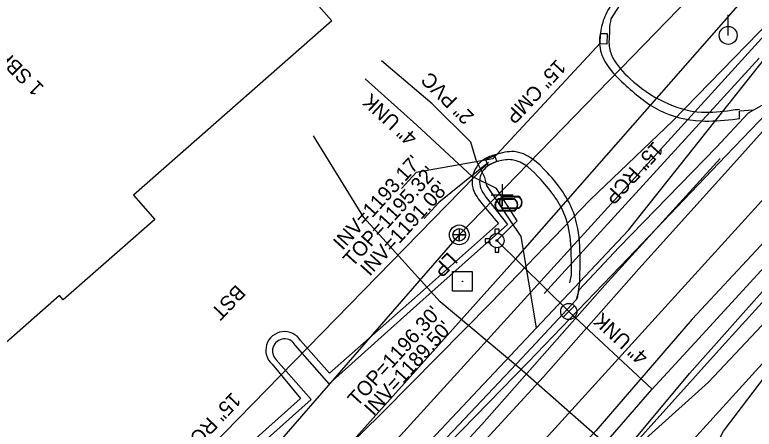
# Model space of a CAD drawing. Extents: x 1263837 to 1268319, y 770628 to 773628.
# Drawn here: x 1266878 to 1267080.4, y 772434.2 to 772547.7 of the extents above; entities that cross this region are included whole.
import ezdxf

# ---------------------------------------------------------------- set-up
doc = ezdxf.new("R2010")
doc.units = 0
for name, color, linetype in [('Exist Building', 7, 'Continuous'), ('Exist Building Text', 7, 'Continuous'), ('Exist DTM Spot Elevation CELL', 7, 'Continuous'), ('Exist Roads EOT Text', 7, 'Continuous'), ('Exist Structure Minor Catch Basin', 7, 'Continuous'), ('Exist Structure Minor Catch Basin Top Elevation', 7, 'Continuous'), ('Exist Utilities Gas UG Line SUE LOS B', 7, 'Continuous'), ('Exist Utilities Gas UG Line SUE LOS B Text', 7, 'Continuous'), ('Exist Utilities Other Pole With Base CELL', 7, 'Continuous'), ('Exist Utilities Other Pole With Base Text', 7, 'Continuous'), ('Exist Utilities Power Pole CELL', 7, 'Continuous'), ('Exist Utilities Telephone UG Cable SUE LOS B', 7, 'Continuous'), ('Exist Utilities Telephone UG FO SUE LOS B', 7, 'Continuous'), ('Exist Utilities TV UG Cable SUE LOS B', 7, 'Continuous'), ('Exist Utilities Water Fire Hydrant CELL', 7, 'Continuous'), ('Exist Utilities Water Meter CELL', 7, 'Continuous'), ('Exist Utilities Water UG Line SUE LOS B', 7, 'Continuous'), ('Exist Utilities Water UG Line SUE LOS B Text', 7, 'Continuous'), ('Exist Utilities Water Valve CELL', 7, 'Continuous'), ('Prop Conc 1ft 6in Curb and Gutter', 7, 'Continuous'), ('Prop Conc 5in Monolithic Keyed In Island', 7, 'Continuous'), ('Prop Drainage Structure Junction Box with Slab Lid Label', 7, 'Continuous'), ('Prop Drainage Structure Pipe RCP 15in Class III Label', 7, 'Continuous'), ('Prop Drainage Structure Pipe RCP 24in Class III Label', 7, 'Continuous'), ('Prop Drainage Structure Pipe Removal Label', 7, 'Continuous'), ('Prop Horizontal Alignment', 7, 'Continuous'), ('Prop Retaining Wall', 7, 'Continuous'), ('Prop SS Fill Line', 7, 'Continuous'), ('Prop SS Fill Text', 7, 'Continuous'), ('Prop SS Transition Line', 7, 'Continuous'), ('Prop WCC CELL', 7, 'Continuous'), ('Prop WCR CELL', 7, 'Continuous'), ('Scratch_Level_2', 7, 'Continuous'), ('Scratch_Level_5', 7, 'Continuous'), ('Typical Terminator CELL', 7, 'Continuous')]:
    doc.layers.add(name, color=color, linetype=linetype)

# ---------------------------------------------------------------- blocks, each defined once
blk = doc.blocks.new('EXIST UTILITIES SANITARY SEWER MANHOLE')
at = {"layer": 'Prop WCR CELL'}
blk.add_lwpolyline([(0, 0.03425), (0, -0.03425), (0, 0), (0.03425, 0), (-0.03425, 0)], dxfattribs=at)
for radius in [0.05389, 0.03425]:
    blk.add_circle((0, 0), radius, dxfattribs=at)
blk = doc.blocks.new('EXIST UTILITIES OTHER POLE WITH BASE')
at = {"layer": 'Exist Utilities Other Pole With Base CELL'}
blk.add_line((0, 0), (0, 0), dxfattribs=at)
blk.add_lwpolyline([(-0.0545, 0.054), (0.0535, 0.054), (0.0535, -0.054), (-0.0545, -0.054), (-0.0545, 0.054)], dxfattribs=at)
blk.add_circle((0, 0), 0.00141, dxfattribs=at)
blk = doc.blocks.new('EXIST DTM SPOT ELEVATION')
at = {"layer": 'Exist DTM Spot Elevation CELL'}
blk.add_lwpolyline([(0, 0.06), (0, -0.06), (0, 0), (0.06, 0), (-0.06, 0)], dxfattribs=at)
blk = doc.blocks.new('EXIST UTILITIES POWER POLE')
at = {"layer": 'Exist Utilities Power Pole CELL'}
for q in [(0, 0.1125), (0, 0)]:
    blk.add_line((0, 0), q, dxfattribs=at)
blk.add_circle((0, 0), 0.049, dxfattribs=at)
blk = doc.blocks.new('EXIST UTILITIES WATER METER')
at = {"layer": 'Exist Utilities Water Meter CELL'}
blk.add_line((0, 0), (0, 0), dxfattribs=at)
for points in [[(-0.0408, 0.034), (0.0408, 0.034)], [(-0.0408, 0.0312), (0.0408, 0.0312)], [(0.0408, -0.0312), (-0.0413, -0.0312)], [(0.0408, -0.034), (-0.0413, -0.034)]]:
    blk.add_lwpolyline(points, dxfattribs=at)
for centre, radius, start, end in [((-0.0261, -0.0001), 0.0371, 113.178, 245.9794), ((-0.0259, -0.0001), 0.0347, 115.3009, 243.7824), ((0.0259, 0), 0.0371, 293.6483, 66.3084), ((0.0261, 0), 0.0345, 295.1272, 64.8728)]:
    blk.add_arc(centre, radius, start, end, dxfattribs=at)
blk = doc.blocks.new('EXIST UTILITIES WATER FIRE HYDRANT')
at = {"layer": 'Exist Utilities Water Fire Hydrant CELL'}
blk.add_line((0, 0), (0, 0), dxfattribs=at)
for points in [[(-0.01025, 0.03825), (-0.01025, 0.064), (0.01025, 0.064), (0.01025, 0.03775)], [(-0.03825, 0.01025), (-0.064, 0.01025), (-0.064, -0.01025), (-0.03825, -0.01025)], [(-0.01025, -0.03825), (-0.01025, -0.064), (0.01025, -0.064), (0.01025, -0.03775)]]:
    blk.add_lwpolyline(points, dxfattribs=at)
for radius in [0.03954, 0.00485]:
    blk.add_circle((0, 0), radius, dxfattribs=at)
blk = doc.blocks.new('EXIST UTILITIES WATER VALVE')
at = {"layer": 'Exist Utilities Water Valve CELL'}
blk.add_lwpolyline([(0.0315, 0.0315), (-0.0315, -0.0315), (0, 0), (0.0315, -0.0315), (-0.0315, 0.0315)], dxfattribs=at)
blk.add_circle((0, 0), 0.0445, dxfattribs=at)

msp = doc.modelspace()

# ---------------------------------------------------------------- linework, layer by layer
at = {"layer": 'Exist Building'}
for p, q in [((1266887.19, 772634.22), (1266964.78, 772546.07)), ((1266964.78, 772546.07), (1266910.49, 772498.29)), ((1266910.49, 772498.29), (1266916.33, 772491.66)), ((1266916.33, 772491.66), (1266891.31, 772469.64)), ((1266890.24, 772470.86), (1266867.63, 772450.96)), ((1266891.31, 772469.64), (1266890.24, 772470.86))]:
    msp.add_line(p, q, dxfattribs=at)
at = {"layer": 'Exist Structure Minor Catch Basin'}
for points in [[(1267038.27, 772539.75), (1267038.36, 772542.6), (1267040.15, 772542.55), (1267040.06, 772539.7)], [(1267006.86, 772508.11), (1267007.48, 772506.58), (1267010, 772507.61), (1267009.38, 772509.13)]]:
    msp.add_lwpolyline(points, close=True, dxfattribs=at)
at = {"layer": 'Exist Utilities Gas UG Line SUE LOS B'}
for points in [[(1267020.79, 772462.03), (1267045.96, 772488.76), (1267078.13, 772529.13), (1267092.32, 772547.17), (1267130.56, 772588.01), (1267171.7, 772635.15), (1267216.72, 772685.42), (1267246.23, 772719.28), (1267260.5, 772735.72), (1267305.1, 772784.15), (1267347.02, 772830.88), (1267365.09, 772851.17), (1267410.96, 772900.49)], [(1267020.79, 772462.03), (1267016.6, 772486.98), (1267007.2, 772500.95), (1267006.67, 772503.14), (1267004.32, 772507.87), (1267002.82, 772512.83), (1266992.27, 772523.31), (1266978.43, 772535.14)], [(1266826.01, 772260.15), (1266857.65, 772289.14), (1266895.03, 772326.45), (1266944.34, 772380.2), (1266987.5, 772426.58), (1267020.79, 772462.03)]]:
    msp.add_lwpolyline(points, dxfattribs=at)
at = {"layer": 'Exist Utilities Telephone UG Cable SUE LOS B'}
for points in [[(1267052.83, 772419.78), (1267044.36, 772426.17), (1267016.25, 772450.85), (1266994.43, 772469.13), (1266973.54, 772492.2), (1266959.83, 772514.6)], [(1266894.85, 772231.77), (1266893.08, 772233.4), (1266890.92, 772236.91), (1266894.43, 772241.95), (1266895.81, 772246.91), (1266901.85, 772256.59), (1266913.6, 772269.64), (1266885.36, 772298.67), (1266907.53, 772324.36), (1266940.1, 772361.84), (1266971, 772397.71), (1267005.88, 772435.55), (1267039.51, 772473.7), (1267071.13, 772508.4)], [(1266894.82, 772231.62), (1266882.54, 772238.29), (1266881.5, 772240.54), (1266906.85, 772271.5), (1266931.58, 772297.61), (1266956.08, 772328.45), (1266980.39, 772357.69), (1266998.14, 772378.22), (1267038.01, 772420.21), (1267067.86, 772447.15), (1267100, 772481.26)]]:
    msp.add_lwpolyline(points, dxfattribs=at)
at = {"layer": 'Exist Utilities Telephone UG FO SUE LOS B'}
for points in [[(1266814.85, 772276.3), (1266828.4, 772281.15), (1266850.03, 772305.04), (1266875.42, 772334.02), (1266901.87, 772361.16), (1266928.35, 772388.2), (1266955.12, 772415.65), (1266978.94, 772439.07), (1267008.37, 772468.81), (1267035.48, 772497.08), (1267058.14, 772518.7), (1267085.04, 772546.33), (1267108.31, 772568.88), (1267130.45, 772592.84), (1267151.19, 772617.71), (1267175.93, 772646.52), (1267201.12, 772673.74)], [(1267052.83, 772419.78), (1267051.59, 772421.75), (1267044.97, 772428.27), (1267062.65, 772449.51), (1267094.39, 772485.05)]]:
    msp.add_lwpolyline(points, dxfattribs=at)
at = {"layer": 'Exist Utilities TV UG Cable SUE LOS B'}
msp.add_lwpolyline([(1267102.75, 772374.47), (1267083.59, 772394.75), (1267068.5, 772408.82), (1267065.38, 772420.99), (1267072, 772433.73), (1267086.74, 772453.14), (1267102.82, 772472.74), (1267112.38, 772485.81), (1267113.95, 772484.12)], dxfattribs=at)
at = {"layer": 'Exist Utilities Water UG Line SUE LOS B'}
msp.add_line((1266955.45, 772414.3), (1267015.09, 772480.76), dxfattribs=at)
for points in [[(1267015.09, 772480.76), (1267121.94, 772602.68), (1267236.76, 772722.91)], [(1267052.51, 772445.25), (1267029.91, 772466.22), (1267010, 772485.88), (1267015.53, 772491.32), (1267009.89, 772500.15), (1267003.25, 772503.41), (1266988.06, 772517.45), (1266973.96, 772530.2)], [(1266929.23, 772298.39), (1266957.23, 772333.47), (1266980.31, 772361.45), (1266995.62, 772381.13), (1267035.16, 772425.19), (1267052.38, 772445.1), (1267064.16, 772457.86), (1267094.36, 772490.84)]]:
    msp.add_lwpolyline(points, dxfattribs=at)
at = {"layer": 'Prop Conc 1ft 6in Curb and Gutter'}
msp.add_lwpolyline([(1267008.89, 772508.23), (1266987.89, 772504.56), (1266983.86, 772500.12)], dxfattribs=at)
at = {"layer": 'Prop Drainage Structure Pipe RCP 15in Class III Label'}
msp.add_line((1267008.89, 772508.23), (1267038.33, 772539.99), dxfattribs=at)
at = {"layer": 'Prop Horizontal Alignment'}
for p, q in [((1267380.31, 772869.08), (1266850.44, 772285.9)), ((1267424.71, 772828.73), (1266891.83, 772242.23))]:
    msp.add_line(p, q, dxfattribs=at)
at = {"layer": 'Prop SS Fill Line'}
msp.add_line((1267029.99, 772474.33), (1267030.36, 772476.51), dxfattribs=at)
for points in [[(1267066.73, 772570.65), (1267043.45, 772550.12), (1267041.19, 772546.57)], [(1267007.07, 772497.65), (1267012.89, 772490.29), (1266988.86, 772468.91), (1266964.04, 772446.67), (1266954.78, 772457.25)], [(1266949.62, 772453.23), (1266959.16, 772442.4), (1266936.95, 772422.6), (1266911.54, 772399.7), (1266902.14, 772410.41)]]:
    msp.add_lwpolyline(points, dxfattribs=at)
msp.add_ellipse((1266951.87, 772455.66), major_axis=(3.31, 0.15), ratio=0.999824, start_param=0.45675, end_param=3.920439, dxfattribs=at)
for points in [[(1267041.19, 772546.57), (1267040.78, 772543.79), (1267040.78, 772542.7), (1267040.67, 772539.5), (1267041.65, 772536.1), (1267046.4, 772530.25), (1267055.72, 772523.84), (1267066.02, 772521.06), (1267074.07, 772521.58), (1267076.38, 772521.9)], [(1267030.36, 772476.51), (1267028.59, 772492.74), (1267022.07, 772502.53), (1267014.15, 772507.99), (1267010.41, 772507.63), (1267006.08, 772504.87), (1267005.39, 772500.8), (1267007.07, 772497.65)]]:
    msp.add_spline(points, degree=3, dxfattribs=at)
at = {"layer": 'Prop SS Fill Text'}
msp.add_line((1267032.03, 772470.01), (1267032.64, 772474.52), dxfattribs=at)
for points in [[(1267204.74, 772651.92), (1267177.02, 772621.14), (1267149.1, 772590.18), (1267145.46, 772586.44), (1267139.98, 772584.67), (1267116.53, 772558.83), (1267115.92, 772554.65), (1267085.25, 772524.39), (1267078.79, 772520.73), (1267070.08, 772511.46), (1267043.47, 772484.13), (1267032.44, 772472.27), (1267031.66, 772469.68), (1267016.92, 772453.79), (1266988.45, 772423.67), (1266964.67, 772398.15), (1266936.57, 772368.17), (1266907.1, 772336.97), (1266877.6, 772304.96), (1266855.4, 772281.41), (1266833.42, 772261.44)], [(1267200.2, 772600.69), (1267172.19, 772569.47), (1267160.06, 772555.77), (1267156.65, 772548.15), (1267144.98, 772534.79), (1267113.45, 772499.8), (1267104.44, 772488.92), (1267097.3, 772485.11), (1267071.59, 772456.86), (1267044.09, 772426.25), (1267018.23, 772397.83), (1266994.88, 772371.31), (1266966.99, 772340.9), (1266937.4, 772307.04), (1266908.92, 772274.6), (1266890.12, 772250.31)], [(1267074.48, 772519.05), (1267076.36, 772519.36), (1267076.38, 772521.4), (1267080.15, 772521.66)], [(1267010.4, 772490.57), (1266987.47, 772470.16), (1266964.18, 772449.6), (1266956.25, 772458.55)], [(1266948.45, 772452.02), (1266956.23, 772442.61), (1266935.48, 772424.05), (1266911.59, 772402.73), (1266903.57, 772411.64)]]:
    msp.add_lwpolyline(points, dxfattribs=at)
msp.add_ellipse((1266951.88, 772455.84), major_axis=(4.89, 1.58), ratio=0.999872, start_param=0.241825, end_param=3.667815, dxfattribs=at)
for points in [[(1267116.93, 772561.74), (1267115.93, 772565.55), (1267112.9, 772570.31), (1267099.69, 772585.79), (1267095.05, 772589.19), (1267090.3, 772590.99), (1267082.64, 772587.45), (1267061.23, 772568.48), (1267042.11, 772551.55), (1267039.51, 772547.26), (1267038.32, 772542.81), (1267038.07, 772539.71), (1267039.53, 772534.94), (1267044.8, 772528.79), (1267054.43, 772521.6), (1267065.76, 772518.65), (1267074.48, 772519.05)], [(1267032.64, 772474.52), (1267030.91, 772493.68), (1267023.84, 772504.43), (1267014.71, 772510.24), (1267009.54, 772509.39), (1267006.56, 772508.17), (1267004.45, 772506.11), (1267003.36, 772500.34), (1267005.55, 772496.44), (1267010.4, 772490.57)]]:
    msp.add_spline(points, degree=3, dxfattribs=at)
at = {"layer": 'Prop SS Transition Line'}
for points in [[(1267395.07, 772827.56), (1267364.93, 772795.4), (1267333.45, 772761.5), (1267304.93, 772730.59), (1267278.73, 772701.98), (1267250.02, 772670.21), (1267221.06, 772638.24), (1267193.05, 772607.16), (1267162.88, 772573.94), (1267133.95, 772541.76), (1267103.89, 772508.37), (1267089.63, 772492.49), (1267063.41, 772464.33), (1267037.06, 772433.84), (1267009.94, 772404.86), (1266986.14, 772378.32), (1266959.27, 772348.06), (1266929.7, 772314.83), (1266900.08, 772282.12), (1266879.74, 772258.85), (1266856.83, 772233.08), (1266828.41, 772200.91)], [(1267146.37, 772585.85), (1267115.99, 772554.09), (1267086.36, 772523.32), (1267072.65, 772509.07), (1267045.87, 772481.1), (1267018.57, 772452.6), (1266989.57, 772422.83), (1266965.51, 772397.48), (1266937.05, 772367.65)], [(1267131.64, 772569.99), (1267100.94, 772535.83), (1267088.17, 772521.91), (1267074.85, 772507.02), (1267048.82, 772478.13), (1267022.71, 772448.59), (1266995.43, 772418.92), (1266970.81, 772392.01), (1266944.06, 772361.6), (1266914.36, 772330.24), (1266883.54, 772297.08), (1266863.59, 772273.71), (1266851.71, 772262.11), (1266827.22, 772236.18), (1266811.72, 772219.25)]]:
    msp.add_lwpolyline(points, dxfattribs=at)
at = {"layer": 'Prop WCC CELL'}
for p, q in [((1267081.79, 772535.83), (1267022.89, 772471.4)), ((1267007.66, 772507.28), (1266857.73, 772353.63))]:
    msp.add_line(p, q, dxfattribs=at)
at = {"layer": 'Scratch_Level_2'}
msp.add_line((1267402.51, 772848.9), (1266783.44, 772167.55), dxfattribs=at)
msp.add_arc((1275094.23, 780056.99), 11459.16, 216.983333, 225.433333, dxfattribs=at)
at = {"layer": 'Scratch_Level_5'}
for q in [(1267258.45, 772754.02), (1266821.09, 772282.38)]:
    msp.add_line((1266999.68, 772487.46), q, dxfattribs=at)
at = {"layer": 'Typical Terminator CELL'}
msp.add_lwpolyline([(1267007.66, 772507.28), (1266994.09, 772496.35), (1266990.06, 772491.91)], dxfattribs=at)

# ---------------------------------------------------------------- block references
at = {"layer": 'Exist DTM Spot Elevation CELL', "xscale": 50, "yscale": 50}
msp.add_blockref('EXIST DTM SPOT ELEVATION', (1267011.42, 772498.33), dxfattribs=at)
at = {"layer": 'Exist Utilities Other Pole With Base CELL', "xscale": 50, "yscale": 50}
msp.add_blockref('EXIST UTILITIES OTHER POLE WITH BASE', (1267000.57, 772474.71), dxfattribs=at)
at = {"layer": 'Exist Utilities Power Pole CELL', "xscale": 50, "yscale": 50}
msp.add_blockref('EXIST UTILITIES POWER POLE', (1267073.29, 772542.07), dxfattribs=at)
at = {"layer": 'Exist Utilities Water Fire Hydrant CELL', "xscale": 50, "yscale": 50}
msp.add_blockref('EXIST UTILITIES WATER FIRE HYDRANT', (1267010, 772485.88), dxfattribs=at)
at = {"layer": 'Exist Utilities Water Meter CELL', "xscale": 50, "yscale": 50}
for p in [(1267012.59, 772495.67), (1267013.75, 772496.34)]:
    msp.add_blockref('EXIST UTILITIES WATER METER', p, dxfattribs=at)
at = {"layer": 'Exist Utilities Water Valve CELL', "xscale": 50, "yscale": 50}
msp.add_blockref('EXIST UTILITIES WATER VALVE', (1267029.67, 772466.47), dxfattribs=at)
at = {"layer": 'Prop WCR CELL', "xscale": 50, "yscale": 50}
msp.add_blockref('EXIST UTILITIES SANITARY SEWER MANHOLE', (1266999.68, 772487.46), dxfattribs=at)

# ---------------------------------------------------------------- texts
at = {"layer": 'Exist Building Text'}
msp.add_text('1 SBKBUS', height=4, rotation=135.4239, dxfattribs=at).set_placement((1266886.28, 772527.95))
at = {"layer": 'Exist Roads EOT Text'}
msp.add_text('BST', height=4, rotation=226.2531, dxfattribs=at).set_placement((1266938.65, 772474.07))
at = {"layer": 'Exist Structure Minor Catch Basin Top Elevation'}
msp.add_text("TOP=1195.32'", height=4, rotation=47.742, dxfattribs=at).set_placement((1266970.46, 772478.44))
at = {"layer": 'Exist Utilities Gas UG Line SUE LOS B Text'}
msp.add_text('2" PVC', height=4, rotation=135.1662, dxfattribs=at).set_placement((1267003.98, 772520.13))
at = {"layer": 'Exist Utilities Other Pole With Base Text'}
msp.add_text('LP', height=4, rotation=226.6901, dxfattribs=at).set_placement((1266996.64, 772483))
at = {"layer": 'Exist Utilities Water UG Line SUE LOS B Text'}
for rotation, p in [(137.2609, (1266988.51, 772514.41)), (137.1513, (1267051.74, 772454.39))]:
    msp.add_text('4" UNK', height=4, rotation=rotation, dxfattribs=at).set_placement(p)
at = {"layer": 'Prop Conc 5in Monolithic Keyed In Island'}
msp.add_text("INV=1193.17'", height=4, rotation=47.742, dxfattribs=at).set_placement((1266967.75, 772483.02))
at = {"layer": 'Prop Drainage Structure Junction Box with Slab Lid Label'}
msp.add_text("INV=1191.08'", height=4, rotation=47.742, dxfattribs=at).set_placement((1266975.16, 772475.94))
at = {"layer": 'Prop Drainage Structure Pipe RCP 24in Class III Label'}
msp.add_text('15" CMP', height=4, rotation=227.178, dxfattribs=at).set_placement((1267026.36, 772535.78))
at = {"layer": 'Prop Drainage Structure Pipe Removal Label'}
for rotation, p in [(227.5701, (1267052.98, 772513.32)), (226.4355, (1266937.48, 772444.59))]:
    msp.add_text('15" RCP', height=4, rotation=rotation, dxfattribs=at).set_placement(p)
at = {"layer": 'Prop Retaining Wall'}
for s, p in [("TOP=1196.30'", (1266971.74, 772440.22)), ("INV=1189.50'", (1266976.21, 772437.67))]:
    msp.add_text(s, height=4, rotation=47.742, dxfattribs=at).set_placement(p)

doc.saveas('drawing.dxf')
